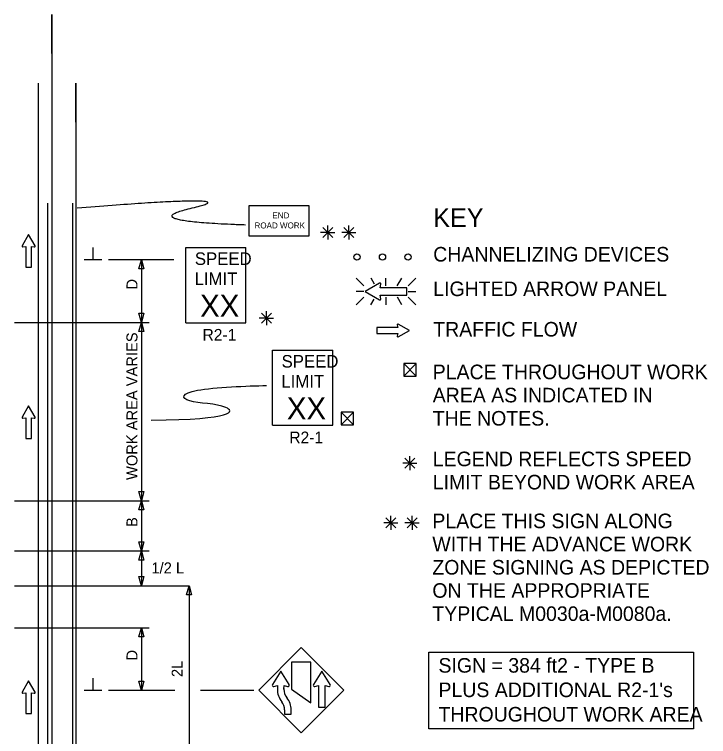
# Model space of a CAD drawing. Extents: x 16741 to 18482, y 7002 to 8333.
# Drawn here: x 16980.8 to 17423.8, y 7872.3 to 8333.1 of the extents above; entities that cross this region are included whole.
import ezdxf

# ---------------------------------------------------------------- set-up
doc = ezdxf.new("R2010")
doc.units = 0
for name, color, linetype in [('ALI_LEGAL_EX', 7, 'Continuous'), ('MT_SCRATCH_LEVEL_E', 7, 'Continuous'), ('PAVT_EDGE_EX', 7, 'Continuous'), ('TRAFFIC_SIGNS_PR', 7, 'Continuous'), ('TYPICAL_TEXT_DIMEN_EX', 7, 'Continuous'), ('TYPICAL_TEXT_DIMEN_PR', 7, 'Continuous')]:
    doc.layers.add(name, color=color, linetype=linetype)

msp = doc.modelspace()

# ---------------------------------------------------------------- linework, layer by layer
at = {"layer": 'ALI_LEGAL_EX'}
for p, q in [((17004.68, 8333.08), (17004.68, 7514.94)), ((16995.95, 8289.26), (16995.95, 7471.12)), ((17019.95, 8289.26), (17019.95, 7471.12))]:
    msp.add_line(p, q, dxfattribs=at)
for points in [[(17004.68, 8308.08), (17004.68, 8333.08)], [(17019.95, 8264.26), (17019.95, 8289.26)]]:
    msp.add_lwpolyline(points, dxfattribs=at)
at = {"layer": 'MT_SCRATCH_LEVEL_E'}
for p, q in [((16989.82, 8192.71), (16985.71, 8185.47)), ((16993.97, 8185.47), (16989.82, 8192.71)), ((16986.19, 8184.79), (16987.97, 8185.1)), ((16987.97, 8185.1), (16987.97, 8171.85)), ((16991.71, 8171.85), (16991.71, 8185.1)), ((16991.71, 8185.1), (16993.49, 8184.79)), ((16987.97, 8171.85), (16991.71, 8171.85)), ((17225.43, 8133.27), (17212.17, 8133.27)), ((17212.17, 8133.27), (17212.17, 8129.53)), ((17225.12, 8135.05), (17225.43, 8133.27)), ((17233.04, 8131.42), (17225.8, 8135.53)), ((17212.17, 8129.53), (17225.43, 8129.53)), ((17225.43, 8129.53), (17225.12, 8127.75)), ((17225.8, 8127.28), (17233.04, 8131.42)), ((16989.82, 8083.36), (16985.71, 8076.12)), ((16993.97, 8076.12), (16989.82, 8083.36)), ((16986.19, 8075.44), (16987.97, 8075.75)), ((16987.97, 8075.75), (16987.97, 8062.5)), ((16991.71, 8062.5), (16991.71, 8075.75)), ((16991.71, 8075.75), (16993.49, 8075.44)), ((16987.97, 8062.5), (16991.71, 8062.5)), ((16989.82, 7907.86), (16985.71, 7900.61)), ((16993.97, 7900.61), (16989.82, 7907.86)), ((16986.19, 7899.93), (16987.97, 7900.24)), ((16987.97, 7900.24), (16987.97, 7886.99)), ((16991.71, 7886.99), (16991.71, 7900.24)), ((16991.71, 7900.24), (16993.49, 7899.93)), ((16987.97, 7886.99), (16991.71, 7886.99))]:
    msp.add_line(p, q, dxfattribs=at)
for centre, start, end in [((16986.12, 8185.25), 150.4248, 279.9638), ((16993.56, 8185.25), 260.0362, 29.7731), ((17225.58, 8135.13), 60.4248, 189.9638), ((17225.58, 8127.69), 170.0362, 299.7731), ((16986.12, 8075.9), 150.4248, 279.9638), ((16993.56, 8075.9), 260.0362, 29.7731), ((16986.12, 7900.39), 150.4248, 279.9638), ((16993.56, 7900.39), 260.0362, 29.7731)]:
    msp.add_arc(centre, 0.463, start, end, dxfattribs=at)
at = {"layer": 'PAVT_EDGE_EX'}
for p, q in [((17001.87, 8212.75), (17001.87, 7557.55)), ((17017.87, 8212.75), (17017.87, 7557.55))]:
    msp.add_line(p, q, dxfattribs=at)
at = {"layer": 'TRAFFIC_SIGNS_PR'}
for p, q in [((17090.18, 8184.37), (17128.58, 8184.37)), ((17090.18, 8136.37), (17090.18, 8184.37)), ((17128.58, 8136.37), (17128.58, 8184.37)), ((17198.85, 8164.8), (17203.79, 8159.87)), ((17210.62, 8160.98), (17208.41, 8164.81)), ((17217.94, 8159.87), (17217.94, 8164.81)), ((17225.17, 8159.87), (17228.02, 8164.81)), ((17232.08, 8159.87), (17237.02, 8164.81)), ((17203.79, 8156.32), (17198.85, 8156.32)), ((17232.08, 8156.32), (17237.02, 8156.32)), ((17198.85, 8147.83), (17203.79, 8152.76)), ((17217.94, 8152.76), (17217.94, 8147.83)), ((17228.06, 8147.83), (17225.22, 8152.76)), ((17232.08, 8152.76), (17237.02, 8147.82)), ((17208.36, 8147.83), (17210.48, 8151.49)), ((17090.18, 8136.37), (17128.58, 8136.37)), ((17145.56, 8118.89), (17183.96, 8118.89)), ((17145.56, 8070.89), (17145.56, 8118.89)), ((17183.96, 8070.89), (17183.96, 8118.89)), ((17145.56, 8070.89), (17183.96, 8070.89)), ((17163.9, 7929.02), (17136.74, 7901.86)), ((17191.05, 7901.86), (17163.9, 7929.02)), ((17136.74, 7901.86), (17163.9, 7874.71)), ((17163.9, 7874.71), (17191.05, 7901.86))]:
    msp.add_line(p, q, dxfattribs=at)
for points in [[(17130.46, 8191.77), (17168.85, 8191.77), (17168.85, 8210.97), (17130.46, 8210.97)], [(17157.58, 7919.8), (17157.58, 7902.45), (17169.99, 7893.83), (17169.99, 7919.8)]]:
    msp.add_lwpolyline(points, close=True, dxfattribs=at)
for points in [[(17213.86, 8161.59), (17204.57, 8156.32), (17213.87, 8150.99)], [(17214.74, 8151.62), (17214.34, 8153.89), (17231.35, 8153.89), (17231.35, 8158.69), (17214.34, 8158.69), (17214.74, 8160.97)], [(17156.09, 7905.57), (17150.76, 7913.94), (17145.43, 7905.57)], [(17182.31, 7905.57), (17176.99, 7913.94), (17171.66, 7905.57)], [(17146.37, 7904.31), (17148.66, 7904.94), (17148.66, 7902.71)], [(17152.85, 7902.6), (17152.86, 7904.94), (17155.15, 7904.31)], [(17172.6, 7904.31), (17174.89, 7904.94), (17174.89, 7891.14), (17179.09, 7891.14), (17179.09, 7904.94), (17181.39, 7904.31)], [(17153.23, 7889.25), (17153.22, 7886.6), (17157.42, 7886.6), (17157.42, 7889.25)]]:
    msp.add_lwpolyline(points, dxfattribs=at)
for centre in [(17199.42, 8178.35), (17215.72, 8178.35), (17232.02, 8178.35)]:
    msp.add_circle(centre, 2, dxfattribs=at)
for centre, radius, start, end in [((17214.15, 8161.07), 0.598, 350.7308, 118.8916), ((17214.15, 8151.52), 0.597, 241.4833, 9.9593), ((17146.14, 7905.12), 0.84, 147.5204, 285.3986), ((17161.25, 7902.34), 12.59, 178.3293, 218.5427), ((17142.36, 7902.94), 10.5, 358.1894, 0.0048), ((17155.38, 7905.12), 0.842, 254.6828, 32.2708), ((17152.38, 7894.18), 10.5, 74.68, 74.6808), ((17164.94, 7911.2), 10.5, 212.4569, 212.4665), ((17172.37, 7905.12), 0.841, 147.5497, 285.3316), ((17181.61, 7905.12), 0.839, 254.6778, 32.4665), ((17191.17, 7911.2), 10.5, 212.4569, 212.4665), ((17161.25, 7902.34), 8.4, 178.1936, 218.5465), ((17144.82, 7889.25), 8.4, 0, 38.5457), ((17144.82, 7889.25), 12.6, 0, 38.5422)]:
    msp.add_arc(centre, radius, start, end, dxfattribs=at)
msp.add_open_spline([(17128.36, 8198.71), (17056.34, 8201), (17132.86, 8218.41), (17020.93, 8209.49)], degree=2, dxfattribs=at)
at = {"layer": 'TYPICAL_TEXT_DIMEN_EX'}
msp.add_lwpolyline([(17245.22, 7926.03), (17414.22, 7926.03), (17414.22, 7877.2), (17245.22, 7877.2)], close=True, dxfattribs=at)
at = {"layer": 'TYPICAL_TEXT_DIMEN_PR'}
for p, q in [((17180.79, 8193.89), (17180.79, 8198.35)), ((17194.3, 8193.89), (17194.3, 8198.35)), ((17180.79, 8193.89), (17176.26, 8193.89)), ((17183.98, 8197.08), (17177.6, 8190.7)), ((17177.61, 8197.08), (17183.98, 8190.7)), ((17180.79, 8193.89), (17183.98, 8193.89)), ((17180.79, 8193.89), (17185.27, 8193.89)), ((17180.79, 8193.89), (17180.79, 8189.39)), ((17194.3, 8193.89), (17189.77, 8193.89)), ((17191.11, 8197.08), (17197.49, 8190.7)), ((17197.49, 8197.08), (17191.11, 8190.7)), ((17194.3, 8193.89), (17197.49, 8193.89)), ((17194.3, 8193.89), (17198.78, 8193.89)), ((17194.3, 8193.89), (17194.3, 8189.39)), ((17030.99, 8176.53), (17030.99, 8184.31)), ((17036.62, 8176.53), (17025.37, 8176.53)), ((17082.51, 8176.53), (17040.87, 8176.53)), ((17060.3, 8170.66), (17061.87, 8176.53)), ((17061.87, 8176.53), (17063.44, 8170.66)), ((17061.87, 8176.53), (17061.87, 8136.53)), ((17061.87, 8170.66), (17060.3, 8170.66)), ((17063.44, 8170.66), (17061.87, 8170.66)), ((17061.87, 8136.53), (17060.3, 8142.39)), ((17060.3, 8142.39), (17061.87, 8142.39)), ((17061.87, 8142.39), (17063.44, 8142.39)), ((17063.44, 8142.39), (17061.87, 8136.53)), ((17138.4, 8142.47), (17144.78, 8136.09)), ((17144.78, 8142.47), (17138.4, 8136.09)), ((17141.59, 8139.28), (17141.59, 8143.74)), ((17141.59, 8139.28), (17137.06, 8139.28)), ((17141.59, 8139.28), (17144.78, 8139.28)), ((17141.59, 8139.28), (17146.07, 8139.28)), ((17141.59, 8139.28), (17141.59, 8134.78)), ((16980.8, 8136.53), (17066.87, 8136.53)), ((17060.3, 8130.66), (17061.87, 8136.53)), ((17061.87, 8136.53), (17061.87, 8022.8)), ((17061.87, 8136.53), (17063.44, 8130.66)), ((17061.87, 8130.66), (17060.3, 8130.66)), ((17063.44, 8130.66), (17061.87, 8130.66)), ((17229.27, 8110.26), (17237.27, 8102.26)), ((17229.27, 8102.26), (17237.27, 8110.26)), ((17189.28, 8071.22), (17197.28, 8079.22)), ((17189.29, 8079.22), (17197.28, 8071.22)), ((17233.23, 8046.69), (17233.23, 8051.15)), ((17233.23, 8046.69), (17228.7, 8046.69)), ((17230.05, 8049.88), (17236.42, 8043.5)), ((17236.42, 8049.88), (17230.05, 8043.5)), ((17233.23, 8046.69), (17236.42, 8046.69)), ((17233.23, 8046.69), (17237.71, 8046.69)), ((17233.23, 8046.69), (17233.23, 8042.19)), ((17061.87, 8022.8), (17060.3, 8028.66)), ((17060.3, 8028.66), (17061.87, 8028.66)), ((17061.87, 8028.66), (17063.44, 8028.66)), ((17063.44, 8028.66), (17061.87, 8022.8)), ((16980.8, 8022.8), (17066.87, 8022.8)), ((17060.3, 8016.94), (17061.87, 8022.8)), ((17061.87, 8022.8), (17061.87, 7990.73)), ((17061.87, 8022.8), (17063.44, 8016.94)), ((17061.87, 8016.94), (17060.3, 8016.94)), ((17063.44, 8016.94), (17061.87, 8016.94)), ((17221.1, 8008.74), (17216.56, 8008.74)), ((17217.91, 8011.93), (17224.28, 8005.56)), ((17224.28, 8011.93), (17217.91, 8005.56)), ((17221.1, 8008.74), (17221.1, 8013.2)), ((17221.1, 8008.74), (17224.28, 8008.74)), ((17221.1, 8008.74), (17225.57, 8008.74)), ((17221.1, 8008.74), (17221.1, 8004.24)), ((17234.6, 8008.74), (17230.07, 8008.74)), ((17237.79, 8011.93), (17231.41, 8005.56)), ((17231.42, 8011.93), (17237.79, 8005.56)), ((17234.6, 8008.74), (17234.6, 8013.2)), ((17234.6, 8008.74), (17237.79, 8008.74)), ((17234.6, 8008.74), (17239.08, 8008.74)), ((17234.6, 8008.74), (17234.6, 8004.24)), ((17061.87, 7990.73), (17060.3, 7996.59)), ((17060.3, 7996.59), (17061.87, 7996.59)), ((17061.87, 7997.82), (17061.87, 7994.22)), ((17061.87, 7996.59), (17063.44, 7996.59)), ((17063.44, 7996.59), (17061.87, 7990.73)), ((16980.8, 7990.73), (17066.87, 7990.73)), ((17060.3, 7984.86), (17061.87, 7990.73)), ((17061.87, 7990.73), (17061.87, 7968.48)), ((17061.87, 7990.73), (17063.44, 7984.86)), ((17061.87, 7984.86), (17060.3, 7984.86)), ((17063.44, 7984.86), (17061.87, 7984.86)), ((17061.87, 7968.48), (17060.3, 7974.34)), ((17060.3, 7974.34), (17061.87, 7974.34)), ((17061.87, 7974.34), (17063.44, 7974.34)), ((17063.44, 7974.34), (17061.87, 7968.48)), ((16980.8, 7968.48), (17092.3, 7968.48)), ((17090.73, 7962.62), (17092.3, 7968.48)), ((17092.3, 7968.48), (17092.3, 7850.6)), ((17092.3, 7968.48), (17093.87, 7962.62)), ((17092.3, 7962.62), (17090.73, 7962.62)), ((17093.87, 7962.62), (17092.3, 7962.62)), ((16980.8, 7941.67), (17066.87, 7941.67)), ((17060.3, 7935.81), (17061.87, 7941.67)), ((17061.87, 7941.67), (17061.87, 7901.67)), ((17061.87, 7941.67), (17063.44, 7935.81)), ((17061.87, 7935.81), (17060.3, 7935.81)), ((17063.44, 7935.81), (17061.87, 7935.81)), ((17030.99, 7901.67), (17030.99, 7909.46)), ((17061.87, 7901.67), (17060.3, 7907.53)), ((17060.3, 7907.53), (17061.87, 7907.53)), ((17061.87, 7907.53), (17063.44, 7907.53)), ((17063.44, 7907.53), (17061.87, 7901.67)), ((17036.62, 7901.67), (17025.37, 7901.67)), ((17083.26, 7901.67), (17040.87, 7901.67)), ((17133.61, 7901.67), (17099.51, 7901.67))]:
    msp.add_line(p, q, dxfattribs=at)
for points in [[(17229.27, 8110.26), (17229.27, 8102.26), (17237.27, 8102.26), (17237.27, 8110.26)], [(17189.29, 8079.22), (17189.28, 8071.22), (17197.28, 8071.22), (17197.28, 8079.22)]]:
    msp.add_lwpolyline(points, close=True, dxfattribs=at)
for points, degree in [([(17068.11, 8074.15), (17121.88, 8074.72), (17121.21, 8084.85), (17086.99, 8084.85), (17086.99, 8094.51), (17129.85, 8096.03), (17141.75, 8096.29)], 3), ([(17326.18, 8047.28), (17326.2, 8047.28), (17326.21, 8047.28), (17326.21, 8047.28)], 2)]:
    msp.add_open_spline(points, degree=degree, dxfattribs=at)

# ---------------------------------------------------------------- texts
at = {"layer": 'TRAFFIC_SIGNS_PR'}
for s, height, p in [('END', 3.831, (17145.46, 8202.9)), ('ROAD WORK', 3.831, (17134.06, 8196.51)), ('SPEED', 8, (17095.95, 8173.23)), ('LIMIT', 8, (17095.79, 8160.43)), ('XX', 14.031, (17099.29, 8140.13)), ('R2-1', 7.44, (17100.86, 8124.93)), ('SPEED', 8, (17151.33, 8107.75)), ('LIMIT', 8, (17151.17, 8094.95)), ('XX', 14.031, (17154.68, 8074.65)), ('R2-1', 7.44, (17156.24, 8059.45))]:
    msp.add_text(s, height=height, dxfattribs=at).set_placement(p)
at = {"layer": 'TYPICAL_TEXT_DIMEN_EX'}
for s, height, p in [('KEY', 12, (17248.11, 8197.45)), ('CHANNELIZING DEVICES', 9.3, (17248.11, 8175.4)), ('LIGHTED ARROW PANEL', 9.3, (17248.11, 8153.35)), ('TRAFFIC FLOW', 9.3, (17248.11, 8127.55)), ('PLACE THROUGHOUT WORK', 9.3, (17247.78, 8100.32)), ('AREA AS INDICATED IN', 9.3, (17247.78, 8085.52)), ('THE NOTES.', 9.3, (17247.78, 8070.72)), ('LEGEND REFLECTS SPEED', 9.3, (17247.79, 8044.79)), ('LIMIT BEYOND WORK AREA', 9.3, (17247.79, 8029.99)), ('PLACE THIS SIGN ALONG', 9.3, (17247.55, 8005.25)), ('WITH THE ADVANCE WORK', 9.3, (17247.55, 7990.45)), ('ZONE SIGNING AS DEPICTED', 9.3, (17247.55, 7975.65)), ('ON THE APPROPRIATE', 9.3, (17247.55, 7960.85)), ('TYPICAL M0030a-M0080a.', 9.3, (17247.55, 7946.05)), ('SIGN = 384 ft2 - TYPE B', 9.3, (17251.45, 7913.06)), ("PLUS ADDITIONAL R2-1's", 9.3, (17251.45, 7897.46)), ('THROUGHOUT WORK AREA', 9.3, (17251.45, 7881.86))]:
    msp.add_text(s, height=height, dxfattribs=at).set_placement(p)
at = {"layer": 'TYPICAL_TEXT_DIMEN_PR'}
for s, p in [('D', (17059.31, 8157.5)), ('WORK AREA VARIES', (17059.31, 8036.02)), ('B', (17059.31, 8006)), ('D', (17059.31, 7920.79)), ('2L', (17088.17, 7910.26))]:
    msp.add_text(s, height=7, rotation=90, dxfattribs=at).set_placement(p)
msp.add_text('1/2 L', height=7, dxfattribs=at).set_placement((17068.27, 7976.4))

doc.saveas('drawing.dxf')
